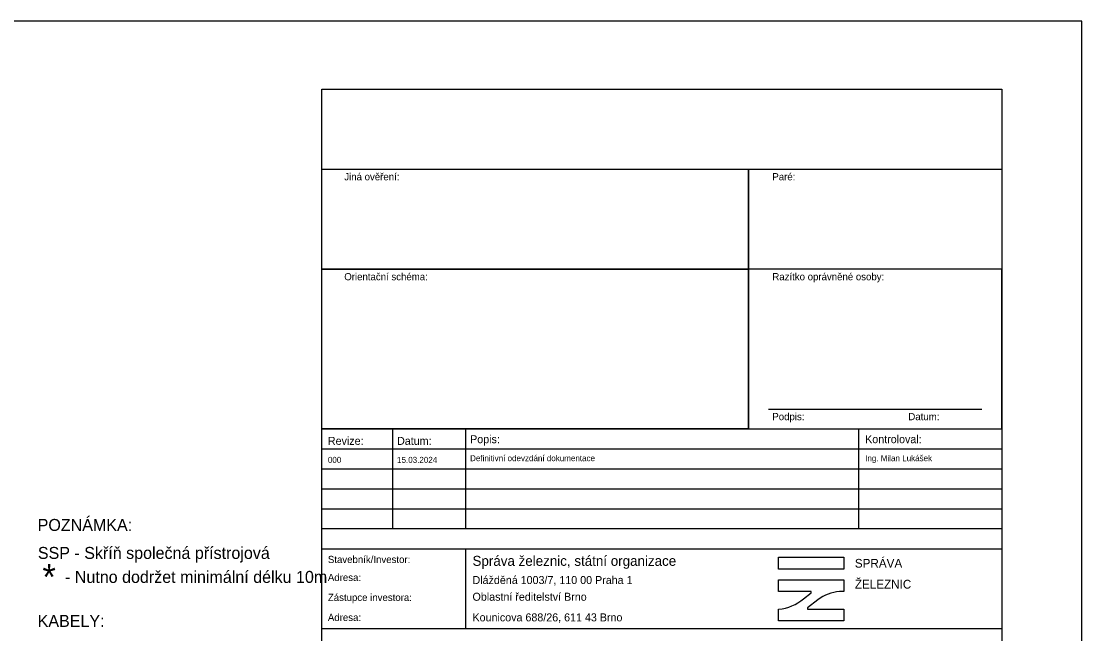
# Model space of a CAD drawing. Extents: x -650084 to -649664, y -1160055 to -1159758.
# Drawn here: x -649929.1 to -649664, y -1159910.7 to -1159757.5 of the extents above; entities that cross this region are included whole.
import ezdxf

# ---------------------------------------------------------------- set-up
doc = ezdxf.new("R2010")
doc.units = 0
for name, color, linetype in [('Default', 7, 'Continuous'), ('Rozpiska_Logo', 7, 'Continuous'), ('Rozpiska_pola_3', 7, 'Continuous'), ('Rozpiska_pole_1', 7, 'Continuous'), ('Rozpiska_pole_2', 7, 'Continuous'), ('Rozpiska_pole_4', 7, 'Continuous'), ('Rozpiska_pole_5', 7, 'Continuous'), ('Rozpiska_pole_6', 7, 'Continuous'), ('Rámečky-tisk', 7, 'Continuous'), ('Vrstva 1', 7, 'Continuous')]:
    doc.layers.add(name, color=color, linetype=linetype)

msp = doc.modelspace()

# ---------------------------------------------------------------- linework, layer by layer
at = {"layer": 'Default'}
msp.add_line((-649747.35, -1159859.5), (-649747.35, -1159794.5), dxfattribs=at)
at = {"layer": 'Rozpiska_Logo'}
for p, q in [((-649733.6, -1159901.97), (-649731.66, -1159900.51)), ((-649731.66, -1159900.51), (-649731.66, -1159900.16)), ((-649729.97, -1159902.24), (-649732.58, -1159904.26)), ((-649732.58, -1159904.26), (-649732.58, -1159904.57))]:
    msp.add_line(p, q, dxfattribs=at)
msp.add_lwpolyline([(-649739.78, -1159891.59), (-649723.48, -1159891.59), (-649723.48, -1159894.52), (-649739.78, -1159894.52)], close=True, dxfattribs=at)
for points in [[(-649731.66, -1159900.16), (-649739.78, -1159900.16), (-649739.78, -1159897.23), (-649723.48, -1159897.23), (-649723.48, -1159900.16), (-649724.56, -1159900.16)], [(-649732.58, -1159904.57), (-649723.48, -1159904.57), (-649723.48, -1159907.5), (-649739.78, -1159907.5), (-649739.78, -1159904.57), (-649739.72, -1159904.57)]]:
    msp.add_lwpolyline(points, dxfattribs=at)
for centre, radius, start, end in [((-649723.82, -1159910.18), 10.04, 94.2142, 127.7808), ((-649740.56, -1159894.08), 10.52, 274.6014, 311.4254)]:
    msp.add_arc(centre, radius, start, end, dxfattribs=at)
at = {"layer": 'Rozpiska_pola_3'}
msp.add_line((-649742.35, -1159854.5), (-649689, -1159854.5), dxfattribs=at)
at = {"layer": 'Rozpiska_pole_1'}
msp.add_lwpolyline([(-649854, -1159774.5), (-649684, -1159774.5), (-649684, -1160039.5), (-649854, -1160039.5)], close=True, dxfattribs=at)
at = {"layer": 'Rozpiska_pole_2'}
for points in [[(-649854, -1159794.5), (-649747.35, -1159794.5), (-649747.35, -1159819.5), (-649854, -1159819.5)], [(-649747.35, -1159794.5), (-649684, -1159794.5), (-649684, -1159819.5), (-649747.35, -1159819.5)], [(-649854, -1159819.5), (-649747.35, -1159819.5), (-649747.35, -1159859.5), (-649854, -1159859.5)], [(-649684, -1159819.5), (-649747.35, -1159819.5), (-649747.35, -1159859.5), (-649684, -1159859.5)]]:
    msp.add_lwpolyline(points, close=True, dxfattribs=at)
at = {"layer": 'Rozpiska_pole_4'}
for p, q in [((-649836.23, -1159884.5), (-649836.23, -1159859.5)), ((-649817.95, -1159884.5), (-649817.95, -1159859.5)), ((-649719.7, -1159884.5), (-649719.7, -1159859.5)), ((-649854, -1159864.5), (-649684, -1159864.5)), ((-649854, -1159869.5), (-649684, -1159869.5)), ((-649854, -1159874.5), (-649684, -1159874.5)), ((-649854, -1159879.5), (-649684, -1159879.5))]:
    msp.add_line(p, q, dxfattribs=at)
msp.add_lwpolyline([(-649854, -1159859.5), (-649684, -1159859.5), (-649684, -1159884.5), (-649854, -1159884.5)], close=True, dxfattribs=at)
at = {"layer": 'Rozpiska_pole_5'}
msp.add_line((-649817.95, -1159909.5), (-649817.95, -1159889.5), dxfattribs=at)
msp.add_lwpolyline([(-649854, -1159889.5), (-649684, -1159889.5), (-649684, -1159909.5), (-649854, -1159909.5)], close=True, dxfattribs=at)
at = {"layer": 'Rámečky-tisk'}
for p, q in [((-649664, -1159757.5), (-650084, -1159757.5)), ((-649664, -1160054.5), (-649664, -1159757.5))]:
    msp.add_line(p, q, dxfattribs=at)

# ---------------------------------------------------------------- texts
at = {"layer": 'Rozpiska_pola_3'}
for s, p in [('Paré:', (-649741.35, -1159797.3)), ('Razítko oprávněné osoby:', (-649741.35, -1159822.3)), ('Podpis:', (-649741.35, -1159857.3)), ('Datum:', (-649707.35, -1159857.3))]:
    msp.add_text(s, height=1.8, dxfattribs=at).set_placement(p)
at = {"layer": 'Rozpiska_pole_2'}
for s, p in [('Jiná ověření:', (-649848.35, -1159797.3)), ('Orientační schéma:', (-649848.35, -1159822.3))]:
    msp.add_text(s, height=1.8, dxfattribs=at).set_placement(p)
at = {"layer": 'Rozpiska_pole_4'}
for s, height, p in [('Revize:', 2, (-649852.45, -1159863.47)), ('Datum:', 2, (-649835.16, -1159863.47)), ('Popis:', 2, (-649816.9, -1159863.05)), ('Kontroloval:', 2, (-649718.15, -1159863.05)), ('000', 1.5, (-649852.45, -1159867.97)), ('15.03.2024', 1.5, (-649835.16, -1159867.97)), ('Definitivní odevzdání dokumentace', 1.5, (-649816.9, -1159867.55)), ('Ing. Milan Lukášek', 1.5, (-649718.15, -1159867.55))]:
    msp.add_text(s, height=height, dxfattribs=at).set_placement(p)
at = {"layer": 'Rozpiska_pole_5'}
for s, height, p in [('Stavebník/Investor:', 1.8, (-649852.45, -1159893.03)), ('Správa železnic, státní organizace', 2.5, (-649816.3, -1159893.73)), ('Adresa:', 1.8, (-649852.45, -1159897.53)), ('Zástupce investora:', 1.8, (-649852.45, -1159902.53)), ('Adresa:', 1.8, (-649852.45, -1159907.53))]:
    msp.add_text(s, height=height, dxfattribs=at).set_placement(p)
at = {"layer": 'Rozpiska_pole_6'}
for s, height, p in [('SPRÁVA', 2.183, (-649720.73, -1159894.18)), ('Dlážděná 1003/7, 110 00 Praha 1', 2, (-649816.3, -1159898.28)), ('ŽELEZNIC', 2.183, (-649720.73, -1159899.41)), ('Oblastní ředitelství Brno', 2, (-649816.3, -1159902.46)), ('Kounicova 688/26, 611 43 Brno', 2, (-649816.3, -1159907.62))]:
    msp.add_text(s, height=height, dxfattribs=at).set_placement(p)
at = {"layer": 'Vrstva 1'}
for s, height, p in [('POZNÁMKA:', 3, (-649925, -1159885)), ('*', 6.4, (-649923.8, -1159899.7)), ('KABELY:', 3, (-649925, -1159909))]:
    msp.add_text(s, height=height, rotation=360, dxfattribs=at).set_placement(p)
for s, p in [('SSP - Skříň společná přístrojová', (-649924.95, -1159892)), ('   - Nutno dodržet minimální délku 10m', (-649921.51, -1159898))]:
    msp.add_text(s, height=3, dxfattribs=at).set_placement(p)

doc.saveas('drawing.dxf')
